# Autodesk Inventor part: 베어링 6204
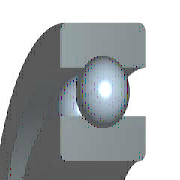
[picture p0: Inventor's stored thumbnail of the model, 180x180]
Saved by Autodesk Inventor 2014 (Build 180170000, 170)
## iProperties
IsCustomPart: 0
Created: 2015-12
Part Number: 베어링 6204
Material: 강철, 연강
Description: 깊은 그루브 볼 베어링
Document SubType Name: Modeling
Standard: KS B 2023
Designer: mdu
Standards Organization: KS
Language: ko-KR
Size Designation: 6204 - 20 x 47 x 14
Categories: <MemberInstance><Categories><Category DisplayName="샤프트 부품" InternalName="7f7aeb1f-a693-4053-b835-cee3144e0d98" Mnemonic="SHFT"><Category DisplayName="베어링" Inter
Density: 7.86 g/cm^3
Mass: 104.255 g
Surface Area: 87.8912 cm^2
Volume: 13.264 cm^3
Appearance: 강철
Author: mud
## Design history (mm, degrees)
sketch "스케치" dims "d0" = 7.02 (= -0.26 x WD + 0.26 x BD)
  geometry: L1 (3.49, 16.75)-(10.51, 16.75); L2 (7, 16.75)-(7, 13.24); L3 (7, 16.75)-(7, 20.26); L4 (4.392, 14.401)-(0, 14.401); L5 (0, 10)-(14, 10); L6 (4.392, 19.099)-(0, 19.099); L7 (0, 23.5)-(14, 23.5); L8 (14, 10)-(14, 14.401); L9 (9.608, 14.401)-(14, 14.401); L10 (9.608, 19.099)-(14, 19.099); L11 (14, 23.5)-(14, 19.099); L12 (-1.4, 0)-(8.4, 0) reference; L13 (0, -0.3)-(0, 5.3) reference
  constraints: 22 end point, 4 point on line, 2 collinear, 2 perpendicular, 2 symmetric about line, 1 midpoint, 1 parallel, 14 other
  dimensions: "d9" = 20 diameter of L5 L12 (= WD); "d11" = 47 diameter of L7 L12 (= BD); "d12" = 14 distance between parallel lines of L8 L13 (= KB); "d13" = 28.802 diameter of L9 L12 (= 0.326 x BD + 0.674 x WD)
revolve "본체" stored, may be unused: angle "d6" = 90 deg
revolve "볼" stored, may be unused: angle "d7" = 90 deg
pattern_circular "IDS_ARRAYBALL[SIMPL:T]" dims angle "d3" = 360 deg
body "Solid1"
fillet "모깎기1" dims "d1" = 1 (= KRS)
other parameters: "WD" = 20 [user parameter; used in 5 equation terms], "BD" = 47 [user parameter; used in 5 equation terms], "KB" = 14 [user parameter; used in 1 equation term], "KRS" = 1 [user parameter; used in 1 equation term], "d4" = 0, "d5" = 0, "d8" = 0, "d14" = 0, "d15" = 0, "BBA" = 0 [user parameter], "BC0" = 6550000 [user parameter], "BC" = 1.27e+07 [user parameter], "BR" = 23.5 (= 0.5 x BD) [user parameter]
